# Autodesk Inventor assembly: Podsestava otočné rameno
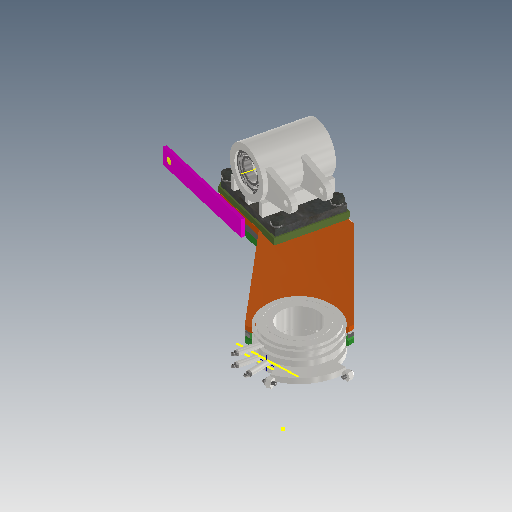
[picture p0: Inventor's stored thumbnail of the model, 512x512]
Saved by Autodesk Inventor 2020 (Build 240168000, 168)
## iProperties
Created: 2025-04
Part Number: Podsestava otočné rameno
Document SubType Name: Assembly
Designer: doma
Author: doma
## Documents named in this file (15)
- C:\Users\doma\Desktop\Pásovka záloha\Workgroups\NotInProject\Podsestava otočné rameno.iam
- C:\Users\doma\Desktop\Pásovka záloha\Workgroups\NotInProject\Svařenec rameno spodní.iam
- C:\Users\doma\Desktop\Pásovka záloha\Workgroups\NotInProject\Svařenec uložení ramene.iam
- C:\Users\doma\Documents\Inventor\Content Center Files\R2020\cs-CZ\CSN 02 4630\CSN 02 4630 - 6206.ipt
- C:\Users\doma\Documents\Inventor\Content Center Files\R2020\cs-CZ\CSN 02 4630\CSN 02 4630 - 6007.ipt
- C:\Users\doma\Documents\Inventor\Content Center Files\R2020\cs-CZ\CSN 02 2931\CSN 02 2931 - 62.ipt
- C:\Users\doma\Desktop\Pásovka záloha\Workgroups\NotInProject\Trubička maznice.ipt
- C:\Users\doma\Documents\Inventor\Content Center Files\R2020\cs-CZ\CSN 02 1741\CSN 02 1741 - 12.ipt
- C:\Users\doma\Documents\Inventor\Content Center Files\R2020\cs-CZ\CSN 02 1703\CSN 02 1703 - 13.ipt
- C:\Users\doma\Documents\Inventor\Content Center Files\R2020\cs-CZ\ISO 4035(2)\ISO 4035 - M6 - ISO.ipt
- C:\Users\doma\Documents\Inventor\Content Center Files\R2020\cs-CZ\ISO 4035(2)\ISO 4035 - M12 - ISO.ipt
- C:\Users\doma\Documents\Inventor\Content Center Files\R2020\cs-CZ\ISO 4018\ISO 4018 - M12 x 55.ipt
- C:\Users\doma\Documents\Inventor\Content Center Files\R2020\cs-CZ\CSN 02 1187\CSN 02 1187 - M6 x 1 x 20.ipt
- C:\Users\doma\Documents\Inventor\Content Center Files\R2020\cs-CZ\CSN 02 7421.2\CSN 02 7421 - M8kuželový krátký.ipt
- C:\Users\doma\Documents\Inventor\Content Center Files\R2020\cs-CZ\ISO 4018\ISO 4018 - M12 x 25.ipt
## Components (30 placed, 14 different names)
1. Svařenec rameno spodní:1 [sub-assembly]
2. Svařenec uložení ramene:1 [sub-assembly] — Proti sobě:26, Proti sobě:27, Proti sobě:28
3. CSN 02 4630 6206:1 — Proti sobě:25, Proti sobě:26, Proti sobě:28
4. CSN 02 4630 6007:1 — Proti sobě:25, Proti sobě:27
5. CSN 02 2931 62:1
6. CSN 02 2931 62:2
7. Trubička maznice:1
8. Trubička maznice:2
9. Trubička maznice:3
10. CSN 02 1741 12:1
11. CSN 02 1741 12:2
12. CSN 02 1741 12:3
13. CSN 02 1741 12:4
14. CSN 02 1703 13:1
15. CSN 02 1703 13:2
16. ISO 4035 M6:1
17. ISO 4035 M6:2
18. ISO 4035 M12:1 — Proti sobě:24
19. ISO 4035 M12:2 — Proti sobě:23
20. ISO 4018 M12 x 25:1
21. ISO 4018 M12 x 25:2
22. ISO 4018 M12 x 25:4
23. ISO 4018 M12 x 25:3
24. ISO 4018 M12 x 55:1 — Proti sobě:23
25. ISO 4018 M12 x 55:2 — Proti sobě:24
26. CSN 02 1187 M6 x 20:1
27. CSN 02 1187 M6 x 20:2
28. CSN 02 7421.2 M8 x 1kuželový krátký:1
29. CSN 02 7421.2 M8 x 1kuželový krátký:2
30. CSN 02 7421.2 M8 x 1kuželový krátký:3
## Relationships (6: Mate 6)
- Proti sobě:23 [Mate]: ISO 4035 M12:2 ↔ ISO 4018 M12 x 55:1
- Proti sobě:24 [Mate]: ISO 4035 M12:1 ↔ ISO 4018 M12 x 55:2
- Proti sobě:25 [Mate]: CSN 02 4630 6206:1 ↔ CSN 02 4630 6007:1
- Proti sobě:26 [Mate]: Svařenec uložení ramene:1 ↔ CSN 02 4630 6206:1
- Proti sobě:27 [Mate]: Svařenec uložení ramene:1 ↔ CSN 02 4630 6007:1
- Proti sobě:28 [Mate]: Svařenec uložení ramene:1 ↔ CSN 02 4630 6206:1
